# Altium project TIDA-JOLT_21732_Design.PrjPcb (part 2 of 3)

## Sheet JOLT_21732_OI_AIN_PWM_check.SchDoc
size 431 x 279 mm; Date: Not shown in title block; ApprovedBy: Not shown in title block; CheckedBy: Not shown in title block; Author: Not shown in title block; CompanyName: Not shown in title block; DrawnBy: X.Gong; Engineer: Not shown in title block; Organization: Not shown in title block; Address1: Not shown in title block; Address2: Not shown in title block; Address3: Not shown in title block; Address4: Not shown in title block; DocumentNumber: 2; Revision: Use project parameter SCH_Rev; SheetNumber: 2; SheetTotal: 5; PageSetup: Record=PageOptions¦CenterHorizontal=True¦CenterVertical=True¦PrintScale=1.00¦XCorrection=1.00¦YCorrection=1.00¦PrintKind=0¦BorderSize=5000000¦LeftOffset=0¦BottomOffset=0¦Orientation=2¦PaperLength=1000¦PaperWidth=1000¦Scale=100¦PaperSource=15¦PrintQuality=600¦MediaType=1¦DitherType=10¦PaperKind=Letter¦PrintScaleMode=1
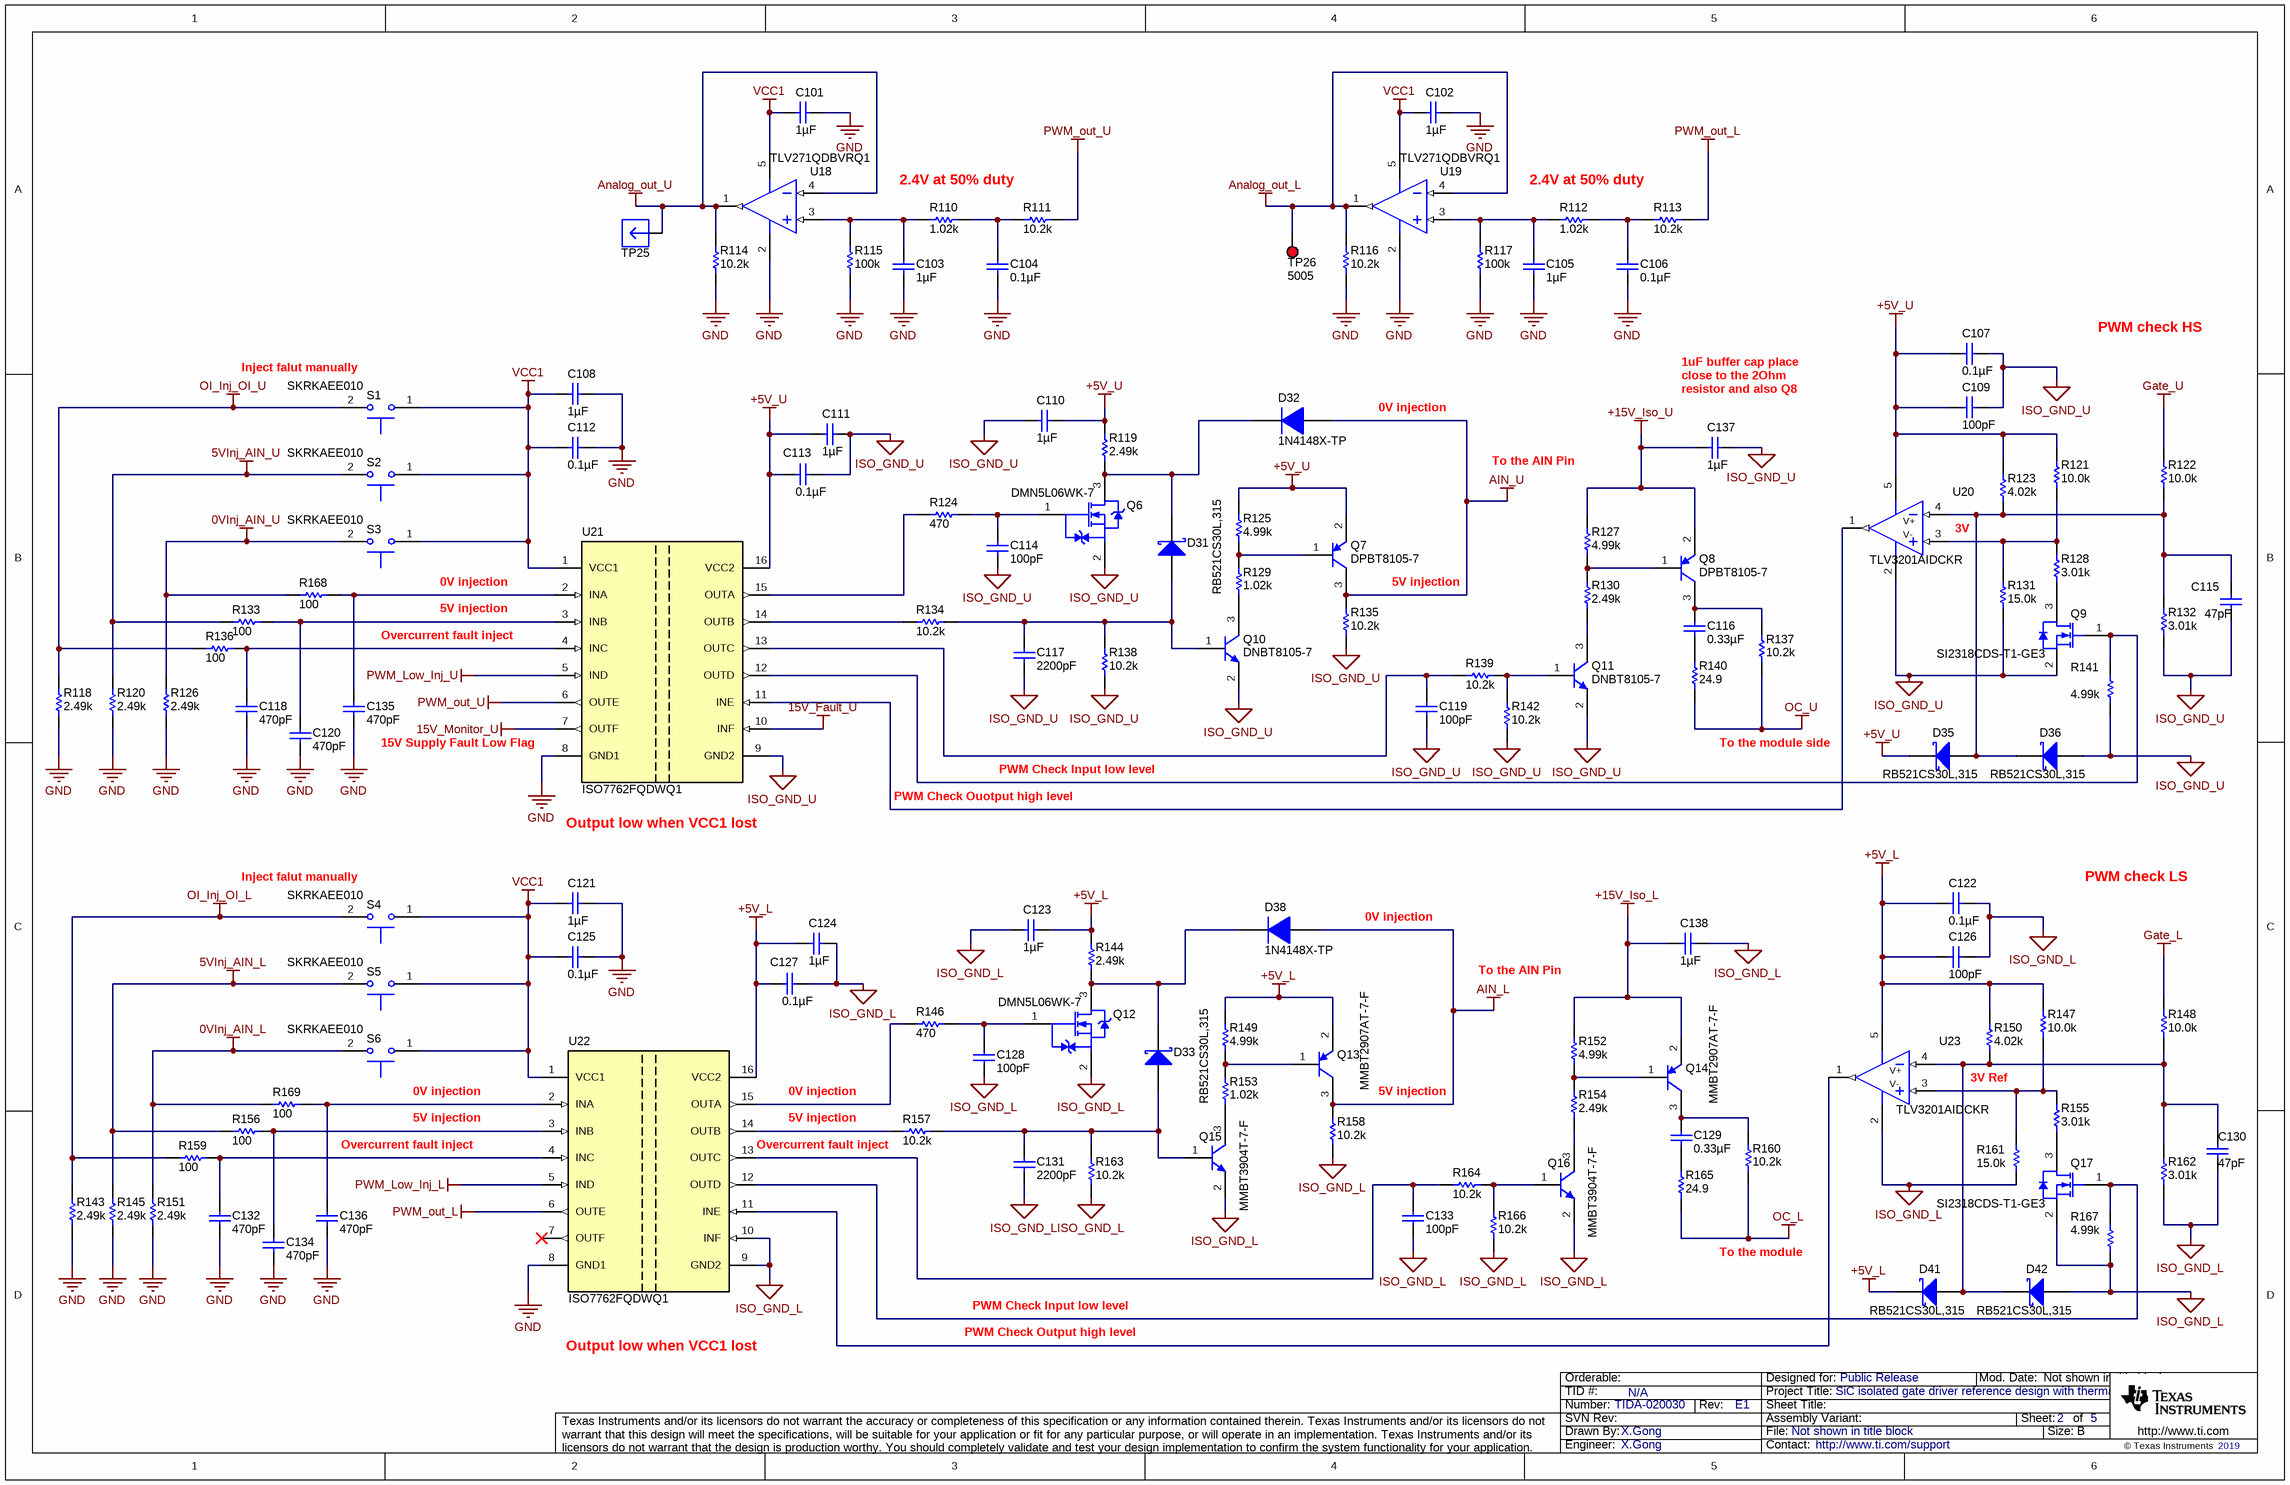
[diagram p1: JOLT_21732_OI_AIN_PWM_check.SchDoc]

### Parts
C101  ValueDisplayed: 1µF  [0603]  (hidden comment: GRM188R71E105KA12D)
C102  ValueDisplayed: 1µF  [0603]  (hidden comment: GRM188R71E105KA12D)
C103  ValueDisplayed: 1µF  [0603]  (hidden comment: GRM188R71E105KA12D)
C104  ValueDisplayed: 0.1µF  [0603]  (hidden comment: GRM188R71H104KA93D)
C105  ValueDisplayed: 1µF  [0603]  (hidden comment: GRM188R71E105KA12D)
C106  ValueDisplayed: 0.1µF  [0603]  (hidden comment: GRM188R71H104KA93D)
C107  ValueDisplayed: 0.1µF  [0603]  (hidden comment: GRM188R71H104KA93D)
C108  ValueDisplayed: 1µF  [0603]  (hidden comment: GRM188R71E105KA12D)
C109  ValueDisplayed: 100pF  [0603]  (hidden comment: GRM1885C1H101JA01D)
C110  ValueDisplayed: 1µF  [0603]  (hidden comment: GRM188R71E105KA12D)
C111  ValueDisplayed: 1µF  [0603]  (hidden comment: GRM188R71E105KA12D)
C112  ValueDisplayed: 0.1µF  [0603]  (hidden comment: GRM188R71H104KA93D)
C113  ValueDisplayed: 0.1µF  [0603]  (hidden comment: GRM188R71H104KA93D)
C114  ValueDisplayed: 100pF  [0603]  (hidden comment: GRM1885C1H101JA01D)
C115  ValueDisplayed: 47pF  [0603]  (hidden comment: GRM1885C1H470JA01D)
C116  ValueDisplayed: 0.33µF  [0805_HV]  (hidden comment: GRM219R71H334KA88D)
C117  ValueDisplayed: 2200pF  [0603]  (hidden comment: GRM188R71E222KA01D)
C118  ValueDisplayed: 470pF  [0603]  (hidden comment: GRM1885C1H471JA01D)
C119  ValueDisplayed: 100pF  [0603]  (hidden comment: GRM1885C1H101JA01D)
C120  ValueDisplayed: 470pF  [0603]  (hidden comment: GRM1885C1H471JA01D)
C121  ValueDisplayed: 1µF  [0603]  (hidden comment: GRM188R71E105KA12D)
C122  ValueDisplayed: 0.1µF  [0603]  (hidden comment: GRM188R71H104KA93D)
C123  ValueDisplayed: 1µF  [0603]  (hidden comment: GRM188R71E105KA12D)
C124  ValueDisplayed: 1µF  [0603]  (hidden comment: GRM188R71E105KA12D)
C125  ValueDisplayed: 0.1µF  [0603]  (hidden comment: GRM188R71H104KA93D)
C126  ValueDisplayed: 100pF  [0603]  (hidden comment: GRM1885C1H101JA01D)
C127  ValueDisplayed: 0.1µF  [0603]  (hidden comment: GRM188R71H104KA93D)
C128  ValueDisplayed: 100pF  [0603]  (hidden comment: GRM1885C1H101JA01D)
C129  ValueDisplayed: 0.33µF  [0805_HV]  (hidden comment: GRM219R71H334KA88D)
C130  ValueDisplayed: 47pF  [0603]  (hidden comment: GRM1885C1H470JA01D)
C131  ValueDisplayed: 2200pF  [0603]  (hidden comment: GRM188R71E222KA01D)
C132  ValueDisplayed: 470pF  [0603]  (hidden comment: GRM1885C1H471JA01D)
C133  ValueDisplayed: 100pF  [0603]  (hidden comment: GRM1885C1H101JA01D)
C134  ValueDisplayed: 470pF  [0603]  (hidden comment: GRM1885C1H471JA01D)
C135  ValueDisplayed: 470pF  [0603]  (hidden comment: GRM1885C1H471JA01D)
C136  ValueDisplayed: 470pF  [0603]  (hidden comment: GRM1885C1H471JA01D)
C137  ValueDisplayed: 1µF  [0603]  (hidden comment: GRM188R71E105KA12D)
C138  ValueDisplayed: 1µF  [0603]  (hidden comment: GRM188R71E105KA12D)
D31  RB521CS30L,315  [SOD882]
D32  1N4148X-TP  [SOD-523]
D33  RB521CS30L,315  [SOD882]
D35  RB521CS30L,315  [SOD882]
D36  RB521CS30L,315  [SOD882]
D38  1N4148X-TP  [SOD-523]
D41  RB521CS30L,315  [SOD882]
D42  RB521CS30L,315  [SOD882]
Q6  DMN5L06WK-7  [SOT-323]
Q7  DPBT8105-7  [SOT-23]
Q8  DPBT8105-7  [SOT-23]
Q9  SI2318CDS-T1-GE3  [SOT-23]
Q10  DNBT8105-7  [SOT-23]
Q11  DNBT8105-7  [SOT-23]
Q12  DMN5L06WK-7  [SOT-323]
Q13  MMBT2907AT-7-F  [SOT-523]
Q14  MMBT2907AT-7-F  [SOT-523]
Q15  MMBT3904T-7-F  [SOT-523]
Q16  MMBT3904T-7-F  [SOT-523]
Q17  SI2318CDS-T1-GE3  [SOT-23]
R110  ValueDisplayed: 1.02k  [0603]  (hidden comment: CRCW06031K02FKEA)
R111  ValueDisplayed: 10.2k  [0603]  (hidden comment: CRCW060310K2FKEA)
R112  ValueDisplayed: 1.02k  [0603]  (hidden comment: CRCW06031K02FKEA)
R113  ValueDisplayed: 10.2k  [0603]  (hidden comment: CRCW060310K2FKEA)
R114  ValueDisplayed: 10.2k  [0603]  (hidden comment: CRCW060310K2FKEA)
R115  ValueDisplayed: 100k  [0603]  (hidden comment: CRCW0603100KFKEA)
R116  ValueDisplayed: 10.2k  [0603]  (hidden comment: CRCW060310K2FKEA)
R117  ValueDisplayed: 100k  [0603]  (hidden comment: CRCW0603100KFKEA)
R118  ValueDisplayed: 2.49k  [0805_HV]  (hidden comment: CRCW08052K49FKEA)
R119  ValueDisplayed: 2.49k  [0805_HV]  (hidden comment: CRCW08052K49FKEA)
R120  ValueDisplayed: 2.49k  [0805_HV]  (hidden comment: CRCW08052K49FKEA)
R121  ValueDisplayed: 10.0k  [0603]  (hidden comment: CRCW060310K0FKEA)
R122  ValueDisplayed: 10.0k  [0805_HV]  (hidden comment: CRCW080510K0FKEA)
R123  ValueDisplayed: 4.02k  [0805_HV]  (hidden comment: CRCW08054K02FKEA)
R124  ValueDisplayed: 470  [0603]  (hidden comment: CRCW0603470RJNEA)
R125  ValueDisplayed: 4.99k  [0603]  (hidden comment: CRCW06034K99FKEA)
R126  ValueDisplayed: 2.49k  [0805_HV]  (hidden comment: CRCW08052K49FKEA)
R127  ValueDisplayed: 4.99k  [0603]  (hidden comment: CRCW06034K99FKEA)
R128  ValueDisplayed: 3.01k  [0805_HV]  (hidden comment: CRCW08053K01FKEA)
R129  ValueDisplayed: 1.02k  [0603]  (hidden comment: CRCW06031K02FKEA)
R130  ValueDisplayed: 2.49k  [0603]  (hidden comment: CRCW06032K49FKEA)
R131  ValueDisplayed: 15.0k  [0603]  (hidden comment: CRCW060315K0FKEA)
R132  ValueDisplayed: 3.01k  [0805_HV]  (hidden comment: CRCW08053K01FKEA)
R133  ValueDisplayed: 100  [0603]  (hidden comment: CRCW0603100RFKEA)
R134  ValueDisplayed: 10.2k  [0603]  (hidden comment: CRCW060310K2FKEA)
R135  ValueDisplayed: 10.2k  [0603]  (hidden comment: CRCW060310K2FKEA)
R136  ValueDisplayed: 100  [0603]  (hidden comment: CRCW0603100RFKEA)
R137  ValueDisplayed: 10.2k  [0603]  (hidden comment: CRCW060310K2FKEA)
R138  ValueDisplayed: 10.2k  [0603]  (hidden comment: CRCW060310K2FKEA)
R139  ValueDisplayed: 10.2k  [0603]  (hidden comment: CRCW060310K2FKEA)
R140  ValueDisplayed: 24.9  [0805_HV]  (hidden comment: CRCW080524R9FKEA)
R141  ValueDisplayed: 4.99k  [0603]  (hidden comment: CRCW06034K99FKEA)
R142  ValueDisplayed: 10.2k  [0603]  (hidden comment: CRCW060310K2FKEA)
R143  ValueDisplayed: 2.49k  [0805_HV]  (hidden comment: CRCW08052K49FKEA)
R144  ValueDisplayed: 2.49k  [0805_HV]  (hidden comment: CRCW08052K49FKEA)
R145  ValueDisplayed: 2.49k  [0805_HV]  (hidden comment: CRCW08052K49FKEA)
R146  ValueDisplayed: 470  [0603]  (hidden comment: CRCW0603470RJNEA)
R147  ValueDisplayed: 10.0k  [0603]  (hidden comment: CRCW060310K0FKEA)
R148  ValueDisplayed: 10.0k  [0805_HV]  (hidden comment: CRCW080510K0FKEA)
R149  ValueDisplayed: 4.99k  [0603]  (hidden comment: CRCW06034K99FKEA)
R150  ValueDisplayed: 4.02k  [0805_HV]  (hidden comment: CRCW08054K02FKEA)
R151  ValueDisplayed: 2.49k  [0805_HV]  (hidden comment: CRCW08052K49FKEA)
R152  ValueDisplayed: 4.99k  [0603]  (hidden comment: CRCW06034K99FKEA)
R153  ValueDisplayed: 1.02k  [0603]  (hidden comment: CRCW06031K02FKEA)
R154  ValueDisplayed: 2.49k  [0603]  (hidden comment: CRCW06032K49FKEA)
R155  ValueDisplayed: 3.01k  [0805_HV]  (hidden comment: CRCW08053K01FKEA)
R156  ValueDisplayed: 100  [0603]  (hidden comment: CRCW0603100RFKEA)
R157  ValueDisplayed: 10.2k  [0603]  (hidden comment: CRCW060310K2FKEA)
R158  ValueDisplayed: 10.2k  [0603]  (hidden comment: CRCW060310K2FKEA)
R159  ValueDisplayed: 100  [0603]  (hidden comment: CRCW0603100RFKEA)
R160  ValueDisplayed: 10.2k  [0603]  (hidden comment: CRCW060310K2FKEA)
R161  ValueDisplayed: 15.0k  [0603]  (hidden comment: CRCW060315K0FKEA)
R162  ValueDisplayed: 3.01k  [0805_HV]  (hidden comment: CRCW08053K01FKEA)
R163  ValueDisplayed: 10.2k  [0603]  (hidden comment: CRCW060310K2FKEA)
R164  ValueDisplayed: 10.2k  [0603]  (hidden comment: CRCW060310K2FKEA)
R165  ValueDisplayed: 24.9  [0805_HV]  (hidden comment: CRCW080524R9FKEA)
R166  ValueDisplayed: 10.2k  [0603]  (hidden comment: CRCW060310K2FKEA)
R167  ValueDisplayed: 4.99k  [0603]  (hidden comment: CRCW06034K99FKEA)
R168  ValueDisplayed: 100  [0603]  (hidden comment: CRCW0603100RFKEA)
R169  ValueDisplayed: 100  [0603]  (hidden comment: CRCW0603100RFKEA)
S1  SKRKAEE010  [SW_SKRKAEE010]
S2  SKRKAEE010  [SW_SKRKAEE010]
S3  SKRKAEE010  [SW_SKRKAEE010]
S4  SKRKAEE010  [SW_SKRKAEE010]
S5  SKRKAEE010  [SW_SKRKAEE010]
S6  SKRKAEE010  [SW_SKRKAEE010]
TP25  0508-0-00-15-00-00-03-0  [Mill-Max_0508-0-00-15-00-00-03-0]  (value not drawn)
TP26  5005  [Keystone5005]
U18  TLV271QDBVRQ1  [DBV0005A_N]
U19  TLV271QDBVRQ1  [DBV0005A_N]
U20  TLV3201AIDCKR  [DCK0005A_N]
U21  ISO7762FQDWQ1  [DW0016B_HV]
U22  ISO7762FQDWQ1  [DW0016B_HV]
U23  TLV3201AIDCKR  [DCK0005A_N]

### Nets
0VInj_AIN_L: R151.1 R169.1 S6.2
0VInj_AIN_U: R126.1 R168.1 S3.2
5VInj_AIN_L: R145.1 R156.1 S5.2
5VInj_AIN_U: R120.1 R133.1 S2.2
15V_Fault_U: U21.10(INF)
15V_Monitor_U: U21.7(OUTF)
+5V_L: C122.2 C123.1 C124.2 C126.1 C127.2 D41.1(K) Q13.2(E) R144.2 R147.2 R149.2 R150.2 U22.16(VCC2) U23.5(V+)
+5V_U: C107.2 C109.1 C110.1 C111.2 C113.2 D35.1(K) Q7.2(E) R119.2 R121.2 R123.2 R125.2 U20.5(V+) U21.16(VCC2)
+15V_Iso_L: C138.1 Q14.2(E) R152.2
+15V_Iso_U: C137.1 Q8.2(E) R127.2
AIN_L: D38.2(A) Q13.3(C) R158.2
AIN_U: D32.2(A) Q7.3(C) R135.2
Analog_out_L: R116.2 TP26.1 U19.1(OUT) U19.4(IN-)
Analog_out_U: R114.2 TP25.1 U18.1(OUT) U18.4(IN-)
Gate_L: R148.2
Gate_U: R122.2
GND: C101.1 C102.1 C103.2 C104.1 C105.2 C106.1 C108.1 C112.2 C118.1 C120.1 C121.1 C125.2 C132.1 C134.1 C135.1 C136.1 R114.1 R115.1 R116.1 R117.1 R118.2 R120.2 R126.2 R143.2 R145.2 R151.2 U18.2(GND) U19.2(GND) U21.8(GND1) U22.8(GND1)
ISO_GND_L: C122.1 C123.2 C124.1 C126.2 C127.1 C128.2 C130.2 C131.2 C133.2 C138.2 D42.2(A) Q12.2(S) Q15.2(E) Q16.2(E) Q17.2(S) R158.1 R161.1 R162.1 R163.1 R166.1 R167.1 U22.9(GND2) U22.10(INF) U23.2(V-)
ISO_GND_U: C107.1 C109.2 C110.2 C111.1 C113.1 C114.2 C115.2 C117.2 C119.2 C137.2 D36.2(A) Q6.2(S) Q9.2(S) Q10.2(E) Q11.2(E) R131.1 R132.1 R135.1 R138.1 R141.1 R142.1 U20.2(V-) U21.9(GND2)
OC_L: R160.1 R165.1
OC_U: R137.1 R140.1
OI_Inj_OI_L: R143.1 R159.1 S4.2
OI_Inj_OI_U: R118.1 R136.1 S1.2
PWM_Low_Inj_L: U22.5(IND)
PWM_Low_Inj_U: U21.5(IND)
PWM_out_L: R113.2 U22.6(OUTE)
PWM_out_U: R111.2 U21.6(OUTE)
VCC1: C101.2 C102.2 C108.2 C112.1 C121.2 C125.1 S1.1 S2.1 S3.1 S4.1 S5.1 S6.1 U18.5(VDD) U19.5(VDD) U21.1(VCC1) U22.1(VCC1)
NetC103_1: C103.1 R110.1 R115.2 U18.3(IN+)
NetC104_2: C104.2 R110.2 R111.1
NetC105_1: C105.1 R112.1 R117.2 U19.3(IN+)
NetC106_2: C106.2 R112.2 R113.1
NetC114_1: C114.1 Q6.1(G) R124.2
NetC115_1: C115.1 D35.2(A) D36.1(K) R122.1 R123.1 R132.2 U20.4(IN-)
NetC116_1: C116.1 Q8.3(C) R137.2
NetC116_2: C116.2 R140.2
NetC117_1: C117.1 D31.2(A) Q10.1(B) R134.2 R138.2
NetC118_2: C118.2 R136.2 U21.4(INC)
NetC119_1: C119.1 R139.1 U21.13(OUTC)
NetC120_2: C120.2 R133.2 U21.3(INB)
NetC128_1: C128.1 Q12.1(G) R146.2
NetC129_1: C129.1 Q14.3(C) R160.2
NetC129_2: C129.2 R165.2
NetC130_1: C130.1 D41.2(A) D42.1(K) R148.1 R150.1 R162.2 U23.4(IN-)
NetC131_1: C131.1 D33.2(A) Q15.1(B) R157.2 R163.2
NetC132_2: C132.2 R159.2 U22.4(INC)
NetC133_1: C133.1 R164.1 U22.13(OUTC)
NetC134_2: C134.2 R156.2 U22.3(INB)
NetC135_2: C135.2 R168.2 U21.2(INA)
NetC136_2: C136.2 R169.2 U22.2(INA)
NetD31_1: D31.1(K) D32.1(K) Q6.3(D) R119.1
NetD33_1: D33.1(K) D38.1(K) Q12.3(D) R144.1
NetQ7_1: Q7.1(B) R125.1 R129.2
NetQ8_1: Q8.1(B) R127.1 R130.2
NetQ9_1: Q9.1(G) R141.2 U21.12(OUTD)
NetQ9_3: Q9.3(D) R128.1
NetQ10_3: Q10.3(C) R129.1
NetQ11_1: Q11.1(B) R139.2 R142.2
NetQ11_3: Q11.3(C) R130.1
NetQ13_1: Q13.1(B) R149.1 R153.2
NetQ14_1: Q14.1(B) R152.1 R154.2
NetQ15_3: Q15.3(C) R153.1
NetQ16_1: Q16.1(B) R164.2 R166.2
NetQ16_3: Q16.3(C) R154.1
NetQ17_1: Q17.1(G) R167.2 U22.12(OUTD)
NetQ17_3: Q17.3(D) R155.1
NetR121_1: R121.1 R128.2 R131.2 U20.3(IN+)
NetR124_1: R124.1 U21.15(OUTA)
NetR134_1: R134.1 U21.14(OUTB)
NetR146_1: R146.1 U22.15(OUTA)
NetR147_1: R147.1 R155.2 R161.2 U23.3(IN+)
NetR157_1: R157.1 U22.14(OUTB)
NetU20_1: U20.1(OUT) U21.11(INE)
NetU22_11: U22.11(INE) U23.1(OUT)

Not connected (* = marked no-connect by the designer): U22 7(OUTF)*

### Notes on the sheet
- 2.4V at 50% duty
- (near S1) Inject falut manually
- PWM check HS
- 0V injection
- (near C137) 1uF buffer cap place close to the 2Ohm resistor and also Q8
- To the AIN Pin
- 3V
- Overcurrent fault inject
- 5V injection
- 15V Supply Fault Low Flag
- PWM Check Input low level
- To the module side
- Output low when VCC1 lost
- PWM Check Ouotput high level
- (near S4) Inject falut manually
- PWM check LS
- (near S6) 0V injection
- (near R150) 3V Ref
- (near R157) Overcurrent fault inject
- To the module
- PWM Check Output high level

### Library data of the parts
C101-C103 C105 C108 C110 C111 C121 C123 C124 C137 C138 = GRM188R71E105KA12D: CAP, CERM, 1 µF, 25 V,+/- 10%, X7R, 0603; Manufacturer: MuRata; Polarized: N; CompType: Capacitor; Value: 1uF; U/M: EA; Cap_F: 0.000001; Tolerance_%: 10; VDC_V: 25; Value2: 25V; TaMin_C: -55; TaMax_C: 125; SizeArea_mm2: 1.28; SizeAreaWB_mm2: 4.68; SizeX_mm: 1.6; SizeY_mm: 0.8; SizeZ_mm: 1; AEC Category: Q200; Green_Lifecycle: Active; Green_REACh: Passed
C104 C106 C107 C112 C113 C122 C125 C127 = GRM188R71H104KA93D: CAP, CERM, 0.1 µF, 50 V,+/- 10%, X7R, 0603; Manufacturer: MuRata; Polarized: N; CompType: Capacitor; Value: 0.1uF; U/M: EA; Cap_F: 0.0000001; Tolerance_%: 10; VDC_V: 50; Value2: 50V; TaMin_C: -55; TaMax_C: 125; SizeArea_mm2: 1.28; SizeAreaWB_mm2: 4.68; SizeX_mm: 1.6; SizeY_mm: 0.8; SizeZ_mm: 1; AEC Category: Q200; Green_Lifecycle: Active; Green_REACh: Passed
C109 C114 C119 C126 C128 C133 = GRM1885C1H101JA01D: CAP, CERM, 100 pF, 50 V,+/- 5%, C0G/NP0, 0603; Manufacturer: MuRata; Polarized: N; CompType: Capacitor; Value: 100pF; U/M: EA; Cap_F: 0.0000000001; Tolerance_%: 5; VDC_V: 50; Value2: 50V; TaMin_C: -55; TaMax_C: 125; SizeArea_mm2: 1.28; SizeAreaWB_mm2: 4.68; SizeX_mm: 1.6; SizeY_mm: 0.8; SizeZ_mm: 1; AEC Category: Q200; Green_Lifecycle: Active; Green_REACh: Passed
C115 C130 = GRM1885C1H470JA01D: CAP, CERM, 47 pF, 50 V,+/- 5%, C0G/NP0, 0603; Manufacturer: MuRata; Polarized: N; CompType: Capacitor; Value: 47pF; U/M: EA; Cap_F: 0.000000000047; Tolerance_%: 5; VDC_V: 50; Value2: 50V; TaMin_C: -55; TaMax_C: 125; SizeArea_mm2: 1.28; SizeAreaWB_mm2: 4.68; SizeX_mm: 1.6; SizeY_mm: 0.8; SizeZ_mm: 1; AEC Category: Q200; Green_Lifecycle: Active; Green_REACh: Passed
C116 C129 = GRM219R71H334KA88D: CAP, CERM, 0.33 µF, 50 V,+/- 10%, X7R, 0805; Manufacturer: MuRata; Polarized: N; CompType: Capacitor; Value: 0.33uF; U/M: EA; Cap_F: 0.00000033; Tolerance_%: 10; VDC_V: 50; Value2: 50V; TaMin_C: -55; TaMax_C: 125; Cap_Case: 0805; SizeArea_mm2: 2.5; SizeAreaWB_mm2: 6.75; SizeX_mm: 2; SizeY_mm: 1.25; SizeZ_mm: 1.45; AEC Category: Q200; Green_Lifecycle: Active; Green_REACh: Passed
C117 C131 = GRM188R71E222KA01D: CAP, CERM, 2200 pF, 25 V,+/- 10%, X7R, 0603; Manufacturer: MuRata; Polarized: N; CompType: Capacitor; Value: 2200pF; U/M: EA; Cap_F: 0.0000000022; Tolerance_%: 10; VDC_V: 25; Value2: 25V; TaMin_C: -55; TaMax_C: 125; SizeArea_mm2: 1.28; SizeAreaWB_mm2: 4.68; SizeX_mm: 1.6; SizeY_mm: 0.8; SizeZ_mm: 1; AEC Category: Q200; Green_Lifecycle: Active; Green_REACh: Passed
C118 C120 C132 C134-C136 = GRM1885C1H471JA01D: CAP, CERM, 470 pF, 50 V,+/- 5%, C0G/NP0, 0603; Manufacturer: MuRata; Polarized: N; CompType: Capacitor; Value: 470pF; U/M: EA; Cap_F: 0.00000000047; Tolerance_%: 5; VDC_V: 50; Value2: 50V; TaMin_C: -55; TaMax_C: 125; SizeArea_mm2: 1.28; SizeAreaWB_mm2: 4.68; SizeX_mm: 1.6; SizeY_mm: 0.8; SizeZ_mm: 1; AEC Category: Q200; Green_Lifecycle: Active; Green_REACh: Passed
D31 D33 D35 D36 D41 D42 = CMP-0028877-2: Diode, Schottky, 30 V, 0.1 A, AEC-Q101, SOD882; Manufacturer: Nexperia; Green_Lifecycle: Not Set; Value2: 0.35V; Vf_V: 3.5dV; Vr_V: 30V; Green_REACh: Incomplete; AEC Category: Q101; Io_A: 1dA; SizeX_mm: 0.985; SizeY_mm: 0.585; SizeArea_mm2: 0.576225; SizeAreaWB_mm2: 3.146225; SizeZ_mm: 0.5; Value: 30V; TJmax_C: 150°C; AEC Qualified: Y; Value1: 0.1A
D32 D38 = CMP-0076957-3: Diode, Switching, 75 V, 0.3 A, SOD-523; Manufacturer: Micro Commercial Components; SizeY_mm: 0.9; Value2: 1.25V; Vr_V: 75V; Value1: 0.3A; Value: 75V; Green_Lifecycle: Not Set; SizeAreaWB_mm2: 5.13; SizeArea_mm2: 1.53; SizeZ_mm: 0.65; Io_A: 3dA; TJmax_C: 150°C; SizeX_mm: 1.7; Green_REACh: Incomplete; AEC Category: Q101
Q6 Q12 = CMP-0000759-1: MOSFET, N-CH, 50 V, 0.3 A, SOT-323; Alternate Manufacturer: None; Manufacturer: Diodes Inc.; SizeZ_mm: 1.1; ChType: N; VdsMax_V: 50V; SizeX_mm: 2.2; Vgs_V: 20V; Value: 50V; SizeArea_mm2: 4.84; AEC Category: Q101; IdsMax_A: 3dA; SizeAreaWB_mm2: 10.24; U/M: EA
Q7 Q8 = CMP-0064870-1: Transistor, PNP, 60 V, 1 A, AEC-Q101, SOT-23; Manufacturer: Diodes Inc.; TaMin_C: -55°C; HfeMax: 300; SizeAreaWB_mm2: 14; Value1: 1 A; Vceo_V: 60V; U/M: EA; Value: 60 V; TaMax_C: 150°C; IcRated_A: 1A; SizeZ_mm: 1.1; SizeX_mm: 2.5; SizeY_mm: 3; SizeArea_mm2: 7.5; CompType: BJT; PNP: 1; AEC Qualified: Y; NPN: 0; Vcesat1_V: 3dV; AEC Category: Q101
Q9 Q17 = CMP-0000739-1: MOSFET, N-CH, 40 V, 5.6 A, SOT-23; Alternate Manufacturer: None; Manufacturer: Vishay-Siliconix; SizeZ_mm: 1.1; ChType: N; Value2: 5.8 nC; Value1: 0.05; VdsMax_V: 40V; SizeX_mm: 2.5; SizeY_mm: 3; Vgs_V: 20V; Value: 40V; Rdson45_ohm: 0.051; SizeArea_mm2: 7.5; AEC Category: Q101; IdsMax_A: 5.6A; SizeAreaWB_mm2: 14; U/M: EA; QgTyp_nC: 5.8
Q10 Q11 = CMP-0064871-1: Transistor, NPN, 60 V, 1 A, AEC-Q101, SOT-23; Manufacturer: Diodes Inc.; TaMin_C: -55°C; HfeMax: 300; Green_Lifecycle: Not Set; SizeAreaWB_mm2: 14; Green_REACh: Incomplete; Value1: 1 A; Vceo_V: 60V; U/M: EA; Value: 60 V; TaMax_C: 150°C; IcRated_A: 1A; SizeZ_mm: 1.1; SizeX_mm: 2.5; SizeY_mm: 3; SizeArea_mm2: 7.5; CompType: BJT; PNP: 0; AEC Qualified: Y; NPN: 1; Vcesat1_V: 2.5dV; AEC Category: Q101
Q13 Q14 = CMP-0000362-2: Transistor, PNP, 60 V, 0.6 A, AEC-Q101, SOT-523; Manufacturer: Diodes Inc.; TaMax_C: 150°C; Value2: 300; Value1: 0.6 A; Vcesat1_V: 4dV; SizeX_mm: 1.6; TaMin_C: -55°C; IcRated_A: 6dA; CompType: BJT; SizeZ_mm: 0.8; AEC Qualified: Y; Value: 60 V; SizeArea_mm2: 2.56; NPN: 0; Vceo_V: 60V; PNP: 1; AEC Category: Q101; SizeAreaWB_mm2: 6.76; U/M: EA
Q15 Q16 = CMP-0000405-2: Transistor, NPN, 40 V, 0.2 A, SOT-523; Manufacturer: Diodes Inc.; TaMax_C: 150°C; Value2: 300; Value1: 0.2 A; Vcesat1_V: 2dV; SizeX_mm: 1.6; TaMin_C: -55°C; IcRated_A: 2dA; CompType: BJT; SizeZ_mm: 0.8; Value: 40 V; SizeArea_mm2: 2.56; NPN: 1; Vceo_V: 40V; PNP: 0; AEC Category: Q101; SizeAreaWB_mm2: 6.76; U/M: EA
R110 R112 R129 R153 = CRCW06031K02FKEA: RES, 1.02 k, 1%, 0.1 W, 0603; Manufacturer: Vishay-Dale; CompType: Resistor; Value: 1.02k; Res_ohm: 1020; Value_Code: 1k02; Tolerance_%: 1; Power_W: 0.1; Value2: 0.1W; VDC_V: 75; TempCo: 100 ppm/C; SizeArea_mm2: 1.28; SizeX_mm: 1.6; SizeY_mm: 0.8; EIA_Code: E96; U/M: EA; AEC Category: Q200; Green_Lifecycle: Active; Green_REACh: Passed
R111 R113 R114 R116 R134 R135 R137-R139 R142 R157 R158 R160 R163 R164 R166 = CRCW060310K2FKEA: RES, 10.2 k, 1%, 0.1 W, 0603; Manufacturer: Vishay-Dale; CompType: Resistor; Value: 10.2k; Res_ohm: 10200; Value_Code: 10k2; Tolerance_%: 1; Power_W: 0.1; Value2: 0.1W; VDC_V: 75; TempCo: 100 ppm/C; SizeArea_mm2: 1.28; SizeX_mm: 1.6; SizeY_mm: 0.8; EIA_Code: E96; U/M: EA; AEC Category: Q200; Green_Lifecycle: Active; Green_REACh: Passed
R115 R117 = CRCW0603100KFKEA: RES, 100 k, 1%, 0.1 W, 0603; Manufacturer: Vishay-Dale; CompType: Resistor; Value: 100k; Res_ohm: 100000; Tolerance_%: 1; Power_W: 0.1; Value2: 0.1W; VDC_V: 75; TempCo: 100 ppm/C; SizeArea_mm2: 1.28; SizeX_mm: 1.6; SizeY_mm: 0.8; EIA_Code: E96; U/M: EA; AEC Category: Q200; Green_Lifecycle: Active; Green_REACh: Passed
R118-R120 R126 R143-R145 R151 = CRCW08052K49FKEA: RES, 2.49 k, 1%, 0.125 W, 0805; Manufacturer: Vishay-Dale; CompType: Resistor; Value: 2.49k; Res_ohm: 2490; Value_Code: 2k49; Tolerance_%: 1; Power_W: 0.125; Value2: 0.125W; VDC_V: 150; TempCo: 100 ppm/C; SizeArea_mm2: 2.5; SizeX_mm: 2; SizeY_mm: 1.25; SizeZ_mm: 1.45; EIA_Code: E96; U/M: EA; AEC Category: Q200; Green_Lifecycle: Active; Green_REACh: Passed
R121 R147 = CRCW060310K0FKEA: RES, 10.0 k, 1%, 0.1 W, 0603; Manufacturer: Vishay-Dale; CompType: Resistor; Value: 10.0k; Res_ohm: 10000; Value_Code: 10k0; Tolerance_%: 1; Power_W: 0.1; Value2: 0.1W; VDC_V: 75; TempCo: 100 ppm/C; SizeArea_mm2: 1.28; SizeX_mm: 1.6; SizeY_mm: 0.8; EIA_Code: E96; U/M: EA; AEC Category: Q200; Green_Lifecycle: Active; Green_REACh: Passed
R122 R148 = CRCW080510K0FKEA: RES, 10.0 k, 1%, 0.125 W, 0805; Manufacturer: Vishay-Dale; CompType: Resistor; Value: 10.0k; Res_ohm: 10000; Value_Code: 10k0; Tolerance_%: 1; Power_W: 0.125; Value2: 0.125W; VDC_V: 150; TempCo: 100 ppm/C; SizeArea_mm2: 2.5; SizeX_mm: 2; SizeY_mm: 1.25; SizeZ_mm: 1.45; EIA_Code: E96; U/M: EA; AEC Category: Q200; Green_Lifecycle: Active; Green_REACh: Passed
R123 R150 = CRCW08054K02FKEA: RES, 4.02 k, 1%, 0.125 W, 0805; Manufacturer: Vishay-Dale; CompType: Resistor; Value: 4.02k; Res_ohm: 4020; Value_Code: 4k02; Tolerance_%: 1; Power_W: 0.125; Value2: 0.125W; VDC_V: 150; TempCo: 100 ppm/C; SizeArea_mm2: 2.5; SizeX_mm: 2; SizeY_mm: 1.25; SizeZ_mm: 1.45; EIA_Code: E96; U/M: EA; AEC Category: Q200; Green_Lifecycle: Active; Green_REACh: Passed
R124 R146 = CRCW0603470RJNEA: RES, 470, 5%, 0.1 W, 0603; Manufacturer: Vishay-Dale; CompType: Resistor; Value: 470; Value_Code: 470R; Tolerance_%: 5; Power_W: 0.1; Value2: 0.1W; VDC_V: 75; TempCo: 200 ppm/C; SizeArea_mm2: 1.28; SizeX_mm: 1.6; SizeY_mm: 0.8; SizeZ_mm: 1; EIA_Code: E24; U/M: EA; AEC Category: Q200; Green_Lifecycle: Active; Green_REACh: Passed
R125 R127 R141 R149 R152 R167 = CRCW06034K99FKEA: RES, 4.99 k, 1%, 0.1 W, 0603; Manufacturer: Vishay-Dale; CompType: Resistor; Value: 4.99k; Res_ohm: 4990; Value_Code: 4k99; Tolerance_%: 1; Power_W: 0.1; Value2: 0.1W; VDC_V: 75; TempCo: 100 ppm/C; SizeArea_mm2: 1.28; SizeX_mm: 1.6; SizeY_mm: 0.8; EIA_Code: E96; U/M: EA; AEC Category: Q200; Green_Lifecycle: Active; Green_REACh: Passed
R128 R132 R155 R162 = CRCW08053K01FKEA: RES, 3.01 k, 1%, 0.125 W, 0805; Manufacturer: Vishay-Dale; CompType: Resistor; Value: 3.01k; Res_ohm: 3010; Value_Code: 3k01; Tolerance_%: 1; Power_W: 0.125; Value2: 0.125W; VDC_V: 150; TempCo: 100 ppm/C; SizeArea_mm2: 2.5; SizeX_mm: 2; SizeY_mm: 1.25; SizeZ_mm: 1.45; EIA_Code: E96; U/M: EA; AEC Category: Q200; Green_Lifecycle: Active; Green_REACh: Passed
R130 R154 = CRCW06032K49FKEA: RES, 2.49 k, 1%, 0.1 W, 0603; Manufacturer: Vishay-Dale; CompType: Resistor; Value: 2.49k; Res_ohm: 2490; Value_Code: 2k49; Tolerance_%: 1; Power_W: 0.1; Value2: 0.1W; VDC_V: 75; TempCo: 100 ppm/C; SizeArea_mm2: 1.28; SizeX_mm: 1.6; SizeY_mm: 0.8; EIA_Code: E96; U/M: EA; AEC Category: Q200; Green_Lifecycle: Active; Green_REACh: Passed
R131 R161 = CRCW060315K0FKEA: RES, 15.0 k, 1%, 0.1 W, 0603; Manufacturer: Vishay-Dale; CompType: Resistor; Value: 15.0k; Res_ohm: 15000; Value_Code: 15k0; Tolerance_%: 1; Power_W: 0.1; Value2: 0.1W; VDC_V: 75; TempCo: 100 ppm/C; SizeArea_mm2: 1.28; SizeX_mm: 1.6; SizeY_mm: 0.8; EIA_Code: E96; U/M: EA; AEC Category: Q200; Green_Lifecycle: Active; Green_REACh: Passed
R133 R136 R156 R159 R168 R169 = CRCW0603100RFKEA: RES, 100, 1%, 0.1 W, 0603; Manufacturer: Vishay-Dale; CompType: Resistor; Value: 100; Value_Code: 100R; Tolerance_%: 1; Power_W: 0.1; Value2: 0.1W; VDC_V: 75; TempCo: 100 ppm/C; SizeArea_mm2: 1.28; SizeX_mm: 1.6; SizeY_mm: 0.8; EIA_Code: E96; U/M: EA; AEC Category: Q200; Green_Lifecycle: Active; Green_REACh: Passed
R140 R165 = CRCW080524R9FKEA: RES, 24.9, 1%, 0.125 W, 0805; Manufacturer: Vishay-Dale; CompType: Resistor; Value: 24.9; Value_Code: 24R9; Tolerance_%: 1; Power_W: 0.125; Value2: 0.125W; VDC_V: 150; TempCo: 100 ppm/C; SizeArea_mm2: 2.5; SizeX_mm: 2; SizeY_mm: 1.25; SizeZ_mm: 1.45; EIA_Code: E96; U/M: EA; AEC Category: Q200; Green_Lifecycle: Active; Green_REACh: Passed
S1-S6 = CMP-0002113-2: Switch, Push Button, SMD; Manufacturer: Alps; CurrentRating_mA: 50A; SwitchFunction: Off-Mom; Circuit: SPST-NO; VDC_V: 12V; PositionCount: 1
TP25 = CMP-0055027-1: PCB Pin, 20mil Dia, Gold, TH; Manufacturer: Mill-Max; CNHeader: FALSE; Gender: Male; CompType: PCB Pin
TP26 = CMP-0055142-1: Test Point, Compact, Red, TH; Manufacturer: Keystone; CNHeader: FALSE; Green_Lifecycle: Active; Green_REACh: Passed; ContactFinish: Silver; CT: TRUE
U18 U19 = CMP-0042686-1: Automotive Catalog 550 uA/Ch, 3 MHz, Rail-to-Rail Output Operational Amplifier, 2.7 to 16 V, -40 to 125 degC, 5-pin SOT23 (DBV5), Green (RoHS & no Sb/Br); Manufacturer: Texas Instruments; Vio (25C)(Max)(mV): 5; CMRR(Min)(dB): 58; Total Supply Voltage(Min)(+5V is 5, +/-5V is 10): 2.7; Packing: LARGE T&R; Iq per channel(Max)(mA): 0.66; Total Supply Voltage(Max)(+5V is 5, +/-5V is 10): 16; Sub Family: Low Supply Voltage Amplifier (<=2.7V), Precision Amplifier; Slew Rate(Typ)(V/us): 2.4; Offset Drift(Typ)(uV/C): 2; GBW(Typ)(MHz): 3; Number of Channels: 1; IIB(Max)(pA): 60
U20 U23 = CMP-0073518-3: 40ns, micro-Power, Rail-to-Rail Input, Single-Channel Comparator with Push-Pull Outputs, DCK0005A (SOT-SC70-5); Alternate PartNumber: TLV3201AIDCKT; Alternate Manufacturer: Texas Instruments; SizeAreaWB_mm2: 9.3; SizeZ_mm: 1.1; SizeX_mm: 2.1; SizeY_mm: 2.0; SizeArea_mm2: 4.2; CompType: IC; AEC Category: Q200; AEC Qualified: N
U21 U22 = CMP-0860136-1: Automotive, High Speed, Robust EMC Six-Channel Digital Isolators, DW0016B (SOIC-16); Alternate Manufacturer: Texas Instruments; Alternate PartNumber: ISO7762FQDWRQ1; SizeAreaWB_mm2: 152.52; SizeY_mm: 10.3; CompType: IC; AEC Qualified: Y; SizeArea_mm2: 107.12; SizeZ_mm: 2.65; AEC Category: Q200; SizeX_mm: 10.4

## Sheet JOLT_21732_DCbus_Thermal_LS.SchDoc
size 431 x 279 mm; Date: Not shown in title block; ApprovedBy: Not shown in title block; CheckedBy: Not shown in title block; Author: Not shown in title block; CompanyName: Not shown in title block; DrawnBy: X.Gong; Engineer: Not shown in title block; Organization: Not shown in title block; Address1: Not shown in title block; Address2: Not shown in title block; Address3: Not shown in title block; Address4: Not shown in title block; DocumentNumber: 3; Revision: Use project parameter SCH_Rev; SheetNumber: 3; SheetTotal: 5; PageSetup: Record=PageOptions¦CenterHorizontal=True¦CenterVertical=True¦PrintScale=1.00¦XCorrection=1.00¦YCorrection=1.00¦PrintKind=0¦BorderSize=5000000¦LeftOffset=0¦BottomOffset=0¦Orientation=2¦PaperLength=1000¦PaperWidth=1000¦Scale=100¦PaperSource=15¦PrintQuality=600¦MediaType=1¦DitherType=10¦PaperKind=Letter¦PrintScaleMode=1
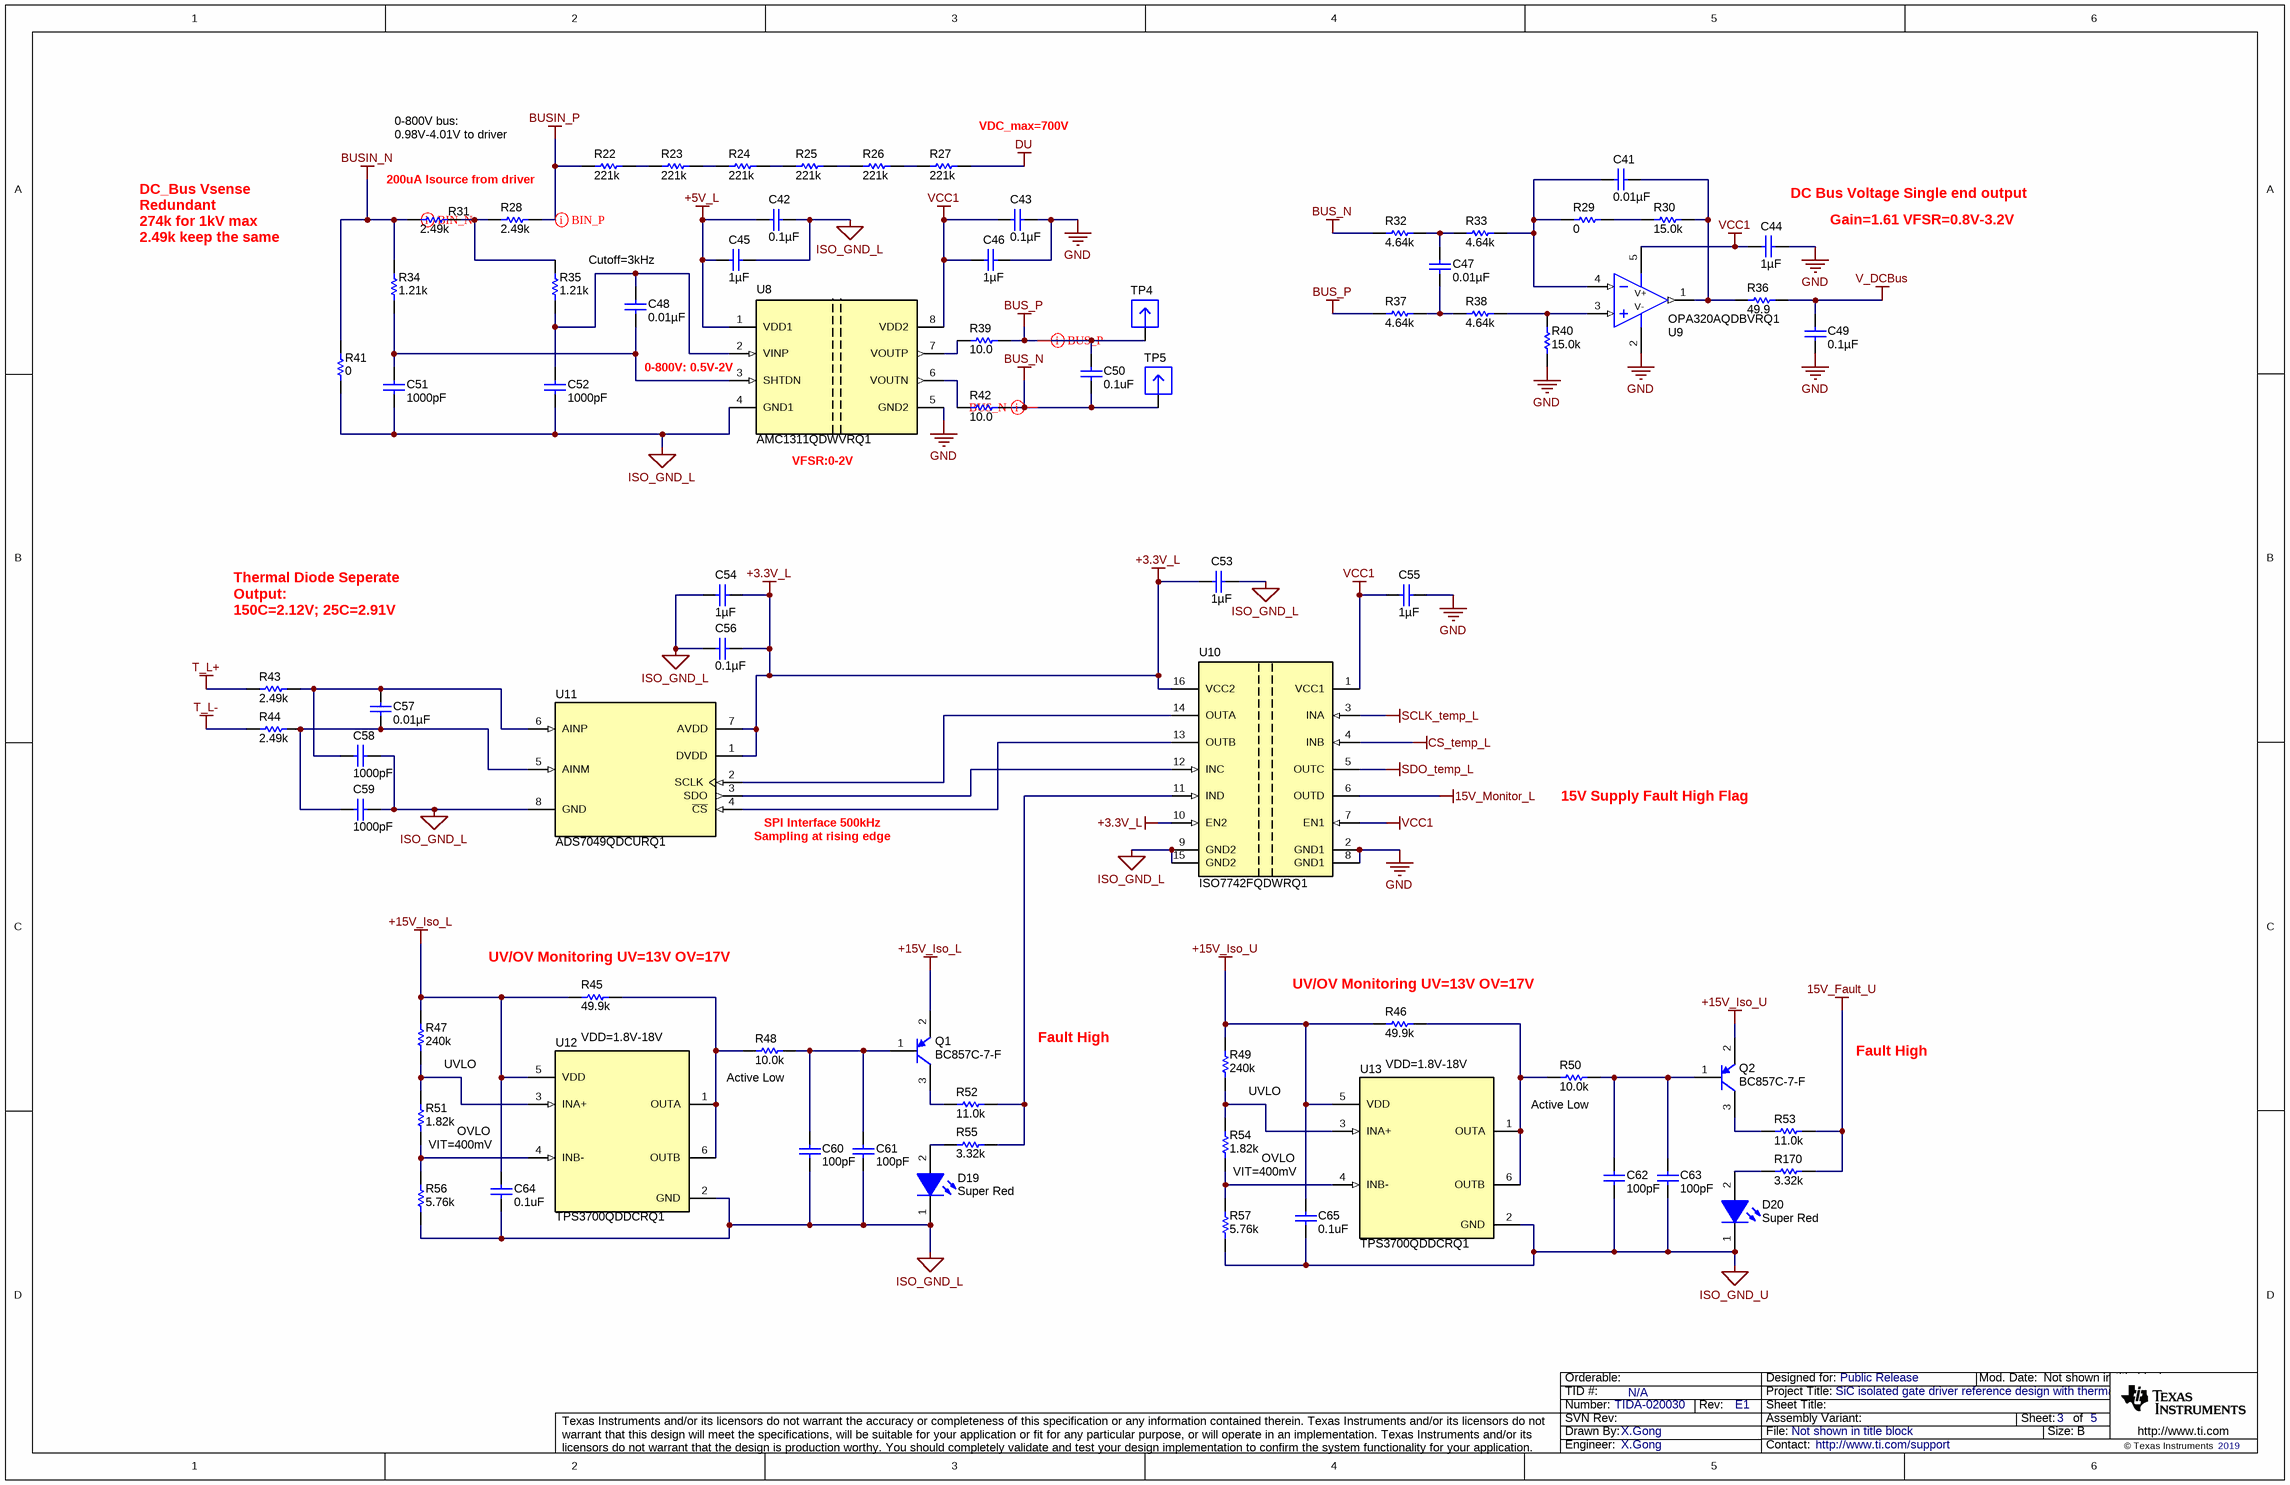
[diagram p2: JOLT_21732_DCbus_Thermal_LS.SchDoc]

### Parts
C41  ValueDisplayed: 0.01µF  [0603]  (hidden comment: GRM188R71H103KA01D)
C42  ValueDisplayed: 0.1µF  [0603]  (hidden comment: GRM188R71H104KA93D)
C43  ValueDisplayed: 0.1µF  [0603]  (hidden comment: GRM188R71H104KA93D)
C44  ValueDisplayed: 1µF  [0603]  (hidden comment: GRM188R71E105KA12D)
C45  ValueDisplayed: 1µF  [0603]  (hidden comment: GRM188R71E105KA12D)
C46  ValueDisplayed: 1µF  [0603]  (hidden comment: GRM188R71E105KA12D)
C47  ValueDisplayed: 0.01µF  [0603]  (hidden comment: GRM188R71H103KA01D)
C48  ValueDisplayed: 0.01µF  [0603]  (hidden comment: GRM188R71H103KA01D)
C49  ValueDisplayed: 0.1µF  [0603]  (hidden comment: GRM188R71H104KA93D)
C50  ValueDisplayed: 0.1uF  [0402]  (hidden comment: Capacitor)
C51  ValueDisplayed: 1000pF  [0603]  (hidden comment: GRM188R71H102KA01D)
C52  ValueDisplayed: 1000pF  [0603]  (hidden comment: GRM188R71H102KA01D)
C53  ValueDisplayed: 1µF  [0603]  (hidden comment: GRM188R71E105KA12D)
C54  ValueDisplayed: 1µF  [0603]  (hidden comment: GRM188R71E105KA12D)
C55  ValueDisplayed: 1µF  [0603]  (hidden comment: GRM188R71E105KA12D)
C56  ValueDisplayed: 0.1µF  [0603]  (hidden comment: GRM188R71H104KA93D)
C57  ValueDisplayed: 0.01µF  [0603]  (hidden comment: GRM188R71H103KA01D)
C58  ValueDisplayed: 1000pF  [0603]  (hidden comment: GRM188R71H102KA01D)
C59  ValueDisplayed: 1000pF  [0603]  (hidden comment: GRM188R71H102KA01D)
C60  ValueDisplayed: 100pF  [0603]  (hidden comment: GRM1885C2A101JA01D)
C61  ValueDisplayed: 100pF  [0603]  (hidden comment: GRM1885C2A101JA01D)
C62  ValueDisplayed: 100pF  [0603]  (hidden comment: GRM1885C2A101JA01D)
C63  ValueDisplayed: 100pF  [0603]  (hidden comment: GRM1885C2A101JA01D)
C64  ValueDisplayed: 0.1uF  [0402]  (hidden comment: Capacitor)
C65  ValueDisplayed: 0.1uF  [0402]  (hidden comment: Capacitor)
D19  value Super Red  [WL-SMCW_RED]  (hidden comment: 150060SS75000)
D20  value Super Red  [WL-SMCW_RED]  (hidden comment: 150060SS75000)
Q1  BC857C-7-F  [SOT-23]
Q2  BC857C-7-F  [SOT-23]
R22  ValueDisplayed: 221k  [1206]  (hidden comment: CRCW1206221KFKEA)
R23  ValueDisplayed: 221k  [1206]  (hidden comment: CRCW1206221KFKEA)
R24  ValueDisplayed: 221k  [1206]  (hidden comment: CRCW1206221KFKEA)
R25  ValueDisplayed: 221k  [1206]  (hidden comment: CRCW1206221KFKEA)
R26  ValueDisplayed: 221k  [1206]  (hidden comment: CRCW1206221KFKEA)
R27  ValueDisplayed: 221k  [1206]  (hidden comment: CRCW1206221KFKEA)
R28  ValueDisplayed: 2.49k  [0805_HV]  (hidden comment: CRCW08052K49FKEA)
R29  ValueDisplayed: 0  [0603]  (hidden comment: CRCW06030000Z0EA)
R30  ValueDisplayed: 15.0k  [0603]  (hidden comment: CRCW060315K0FKEA)
R31  ValueDisplayed: 2.49k  [0805_HV]  (hidden comment: CRCW08052K49FKEA)
R32  ValueDisplayed: 4.64k  [0603]  (hidden comment: CRCW06034K64FKEA)
R33  ValueDisplayed: 4.64k  [0603]  (hidden comment: CRCW06034K64FKEA)
R34  ValueDisplayed: 1.21k  [0603]  (hidden comment: CRCW06031K21FKEA)
R35  ValueDisplayed: 1.21k  [0603]  (hidden comment: CRCW06031K21FKEA)
R36  ValueDisplayed: 49.9  [0603]  (hidden comment: CRCW060349R9FKEA)
R37  ValueDisplayed: 4.64k  [0603]  (hidden comment: CRCW06034K64FKEA)
R38  ValueDisplayed: 4.64k  [0603]  (hidden comment: CRCW06034K64FKEA)
R39  ValueDisplayed: 10.0  [0402]  (hidden comment: CRCW040210R0FKED)
R40  ValueDisplayed: 15.0k  [0603]  (hidden comment: CRCW060315K0FKEA)
R41  ValueDisplayed: 0  [0402]  (hidden comment: CRCW04020000Z0ED)
R42  ValueDisplayed: 10.0  [0402]  (hidden comment: CRCW040210R0FKED)
R43  ValueDisplayed: 2.49k  [0603]  (hidden comment: CRCW06032K49FKEA)
R44  ValueDisplayed: 2.49k  [0603]  (hidden comment: CRCW06032K49FKEA)
R45  ValueDisplayed: 49.9k  [0402]  (hidden comment: CRCW040249K9FKED)
R46  ValueDisplayed: 49.9k  [0402]  (hidden comment: CRCW040249K9FKED)
R47  ValueDisplayed: 240k  [0402]  (hidden comment: CRCW0402240KFKED)
R48  ValueDisplayed: 10.0k  [0402]  (hidden comment: CRCW040210K0FKED)
R49  ValueDisplayed: 240k  [0402]  (hidden comment: CRCW0402240KFKED)
R50  ValueDisplayed: 10.0k  [0402]  (hidden comment: CRCW040210K0FKED)
R51  ValueDisplayed: 1.82k  [0402]  (hidden comment: CRCW04021K82FKED)
R52  ValueDisplayed: 11.0k  [0603]  (hidden comment: CRCW060311K0FKEA)
R53  ValueDisplayed: 11.0k  [0603]  (hidden comment: CRCW060311K0FKEA)
R54  ValueDisplayed: 1.82k  [0402]  (hidden comment: CRCW04021K82FKED)
R55  ValueDisplayed: 3.32k  [0603]  (hidden comment: CRCW06033K32FKEA)
R56  ValueDisplayed: 5.76k  [0402]  (hidden comment: CRCW04025K76FKED)
R57  ValueDisplayed: 5.76k  [0402]  (hidden comment: CRCW04025K76FKED)
R170  ValueDisplayed: 3.32k  [0603]  (hidden comment: CRCW06033K32FKEA)
TP4  0508-0-00-15-00-00-03-0  [Mill-Max_0508-0-00-15-00-00-03-0]  (value not drawn)
TP5  0508-0-00-15-00-00-03-0  [Mill-Max_0508-0-00-15-00-00-03-0]  (value not drawn)
U8  PartNumber: AMC1311QDWVRQ1  [DWV0008A]  (hidden comment: AMC1311DWVR)
U9  OPA320AQDBVRQ1  [DBV0005A_N]
U10  ISO7742FQDWRQ1  [DW0016B_HV]
U11  ADS7049QDCURQ1  [DCU0008A_N]
U12  TPS3700QDDCRQ1  [DDC0006A_N]
U13  TPS3700QDDCRQ1  [DDC0006A_N]

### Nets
15V_Fault_U: R53.2 R170.2
15V_Monitor_L: U10.6(OUTD)
+3.3V_L: C53.2 C54.1 C56.2 U10.10(EN2) U10.16(VCC2) U11.1(DVDD) U11.7(AVDD)
+5V_L: C42.1 C45.2 U8.1(VDD1)
+15V_Iso_L: C64.1 Q1.2(E) R45.1 R47.2 U12.5(VDD)
+15V_Iso_U: C65.1 Q2.2(E) R46.1 R49.2 U13.5(VDD)
BUS_N: C50.2 R32.1 R42.1 TP5.1
BUS_P: C50.1 R37.1 R39.1 TP4.1
BUSIN_N: R31.1 R34.2 R41.2
BUSIN_P: R22.1 R28.2
CS_temp_L: U10.4(INB)
DU: R27.2
GND: C43.2 C44.1 C46.1 C49.2 C55.1 R40.1 U8.5(GND2) U9.2(V-) U10.2(GND1) U10.8(GND1)
ISO_GND_L: C42.2 C45.1 C51.2 C52.2 C53.1 C54.2 C56.1 C58.1 C59.1 C60.2 C61.2 C64.2 D19.1(K) R41.1 R56.1 U8.4(GND1) U10.9(GND2) U10.15(GND2) U11.8(GND) U12.2(GND)
ISO_GND_U: C62.2 C63.2 C65.2 D20.1(K) R57.1 U13.2(GND)
SCLK_temp_L: U10.3(INA)
SDO_temp_L: U10.5(OUTC)
T_L+: R43.1
T_L-: R44.1
V_DCBus: C49.1 R36.1
VCC1: C43.1 C44.2 C46.2 C55.2 U8.8(VDD2) U9.5(V+) U10.1(VCC1) U10.7(EN1)
NetC41_1: C41.1 R29.1 R33.2 U9.4(IN-)
NetC41_2: C41.2 R30.2 R36.2 U9.1(OUT)
NetC47_1: C47.1 R32.2 R33.1
NetC47_2: C47.2 R37.2 R38.1
NetC48_1: C48.1 C51.1 R34.1 U8.3(SHTDN)
NetC48_2: C48.2 C52.1 R35.1 U8.2(VINP)
NetC57_1: C57.1 C59.2 R44.2 U11.5(AINM)
NetC57_2: C57.2 C58.2 R43.2 U11.6(AINP)
NetC60_1: C60.1 C61.1 Q1.1(B) R48.2
NetC62_1: C62.1 C63.1 Q2.1(B) R50.2
NetD19_2: D19.2(A) R55.1
NetD20_2: D20.2(A) R170.1
NetQ1_3: Q1.3(C) R52.1
NetQ2_3: Q2.3(C) R53.1
NetR22_2: R22.2 R23.1
NetR23_2: R23.2 R24.1
NetR24_2: R24.2 R25.1
NetR25_2: R25.2 R26.1
NetR26_2: R26.2 R27.1
NetR28_1: R28.1 R31.2 R35.2
NetR29_2: R29.2 R30.1
NetR38_2: R38.2 R40.2 U9.3(IN+)
NetR39_2: R39.2 U8.7(VOUTP)
NetR42_2: R42.2 U8.6(VOUTN)
NetR45_2: R45.2 R48.1 U12.1(OUTA) U12.6(OUTB)
NetR46_2: R46.2 R50.1 U13.1(OUTA) U13.6(OUTB)
NetR47_1: R47.1 R51.2 U12.3(INA+)
NetR49_1: R49.1 R54.2 U13.3(INA+)
NetR51_1: R51.1 R56.2 U12.4(INB-)
NetR52_2: R52.2 R55.2 U10.11(IND)
NetR54_1: R54.1 R57.2 U13.4(INB-)
NetU10_12: U10.12(INC) U11.3(SDO)
NetU10_13: U10.13(OUTB) U11.4(~{CS})
NetU10_14: U10.14(OUTA) U11.2(SCLK)

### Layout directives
differential pair: BUS_N, BUS_P, BUSIN_N, BUSIN_P

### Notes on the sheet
- 0-800V bus:
  0.98V-4.01V to driver
- (near R27) VDC_max=700V
- 200uA Isource from driver
- (near C44) DC Bus Voltage Single end output
- Gain=1.61 VFSR=0.8V-3.2V
- DC_Bus Vsense Redundant
  274k for 1kV max
  2.49k keep the same
- Cutoff=3kHz
- (near U8) 0-800V: 0.5V-2V
- (near U8) VFSR:0-2V
- Thermal Diode Seperate
  Output:
  150C=2.12V; 25C=2.91V
- (near U11) SPI Interface 500kHz
- (near U11) Sampling at rising edge
- 15V Supply Fault High Flag
- (near R45) UV/OV Monitoring UV=13V OV=17V
- VDD=1.8V-18V
- Fault High
- (near R46) UV/OV Monitoring UV=13V OV=17V
- UVLO
- (near R48) Active Low
- (near R50) Active Low
- (near R51) VIT=400mV
- OVLO
- (near R54) VIT=400mV

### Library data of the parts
C41 C47 C48 C57 = GRM188R71H103KA01D: CAP, CERM, 0.01 µF, 50 V,+/- 10%, X7R, 0603; Manufacturer: MuRata; Polarized: N; CompType: Capacitor; Value: 0.01uF; U/M: EA; Cap_F: 0.00000001; Tolerance_%: 10; VDC_V: 50; Value2: 50V; TaMin_C: -55; TaMax_C: 125; SizeArea_mm2: 1.28; SizeAreaWB_mm2: 4.68; SizeX_mm: 1.6; SizeY_mm: 0.8; SizeZ_mm: 1; AEC Category: Q200; Green_Lifecycle: Active; Green_REACh: Passed
C42 C43 C49 C56 = GRM188R71H104KA93D: as C104 on sheet JOLT_21732_OI_AIN_PWM_check
C44-C46 C53-C55 = GRM188R71E105KA12D: as C101-C103 on sheet JOLT_21732_OI_AIN_PWM_check
C50 = CMP-0006297-2: CAP, CERM, 0.1 uF, 50 V, +/- 10%, X7R, 0402; PartNumber: C1005X7R1H104K050BB; Manufacturer: TDK; Polarized: N; Value: 0.1uF; U/M: EA; Cap_F: 100nF; ESR_ohm: 0.039064; Value1: 0.039064 ohm; VDC_V: 50V; IRMS_A: 8.14669dA; TaMin_C: -55°C; TaMax_C: 125°C; SizeArea_mm2: 0.5; SizeAreaWB_mm2: 3; SizeX_mm: 1; SizeZ_mm: 0.6; AEC Category: Q200
C51 C52 C58 C59 = GRM188R71H102KA01D: CAP, CERM, 1000 pF, 50 V,+/- 10%, X7R, 0603; Manufacturer: MuRata; Polarized: N; CompType: Capacitor; Value: 1000pF; U/M: EA; Cap_F: 0.000000001; Tolerance_%: 10; VDC_V: 50; Value2: 50V; TaMin_C: -55; TaMax_C: 125; SizeArea_mm2: 1.28; SizeAreaWB_mm2: 4.68; SizeX_mm: 1.6; SizeY_mm: 0.8; SizeZ_mm: 1; AEC Category: Q200; Green_Lifecycle: Active; Green_REACh: Passed
C60-C63 = GRM1885C2A101JA01D: CAP, CERM, 100 pF, 100 V,+/- 5%, C0G/NP0, 0603; Manufacturer: MuRata; Polarized: N; CompType: Capacitor; Value: 100pF; U/M: EA; Cap_F: 0.0000000001; Tolerance_%: 5; VDC_V: 100; Value2: 100V; TaMin_C: -55; TaMax_C: 125; SizeArea_mm2: 1.28; SizeAreaWB_mm2: 4.68; SizeX_mm: 1.6; SizeY_mm: 0.8; SizeZ_mm: 1; AEC Category: Q200; Green_Lifecycle: Active; Green_REACh: Passed
C64 C65 = CMP-0006562-2: CAP, CERM, 0.1 uF, 10 V, +/- 10%, X5R, 0402; PartNumber: GRM155R61A104KA01D; Manufacturer: MuRata; Polarized: N; Value: 0.1uF; U/M: EA; Cap_F: 100nF; Value1: Unknown; VDC_V: 10V; TaMin_C: -55°C; TaMax_C: 85°C; SizeArea_mm2: 0.5; SizeAreaWB_mm2: 3; SizeX_mm: 1; SizeZ_mm: 0.6; AEC Category: Q200
D19 D20 = 150060SS75000: LED, Super Red, SMD; Manufacturer: Wurth Elektronik; Type: AlInGaP; Vf_V: 1.9; Value2: 1.9V; Io_A: 0.02; Value1: W; U/M: EA; Green_Lifecycle: Active; Green_REACh: Passed
Q1 Q2 = BC857C-7-F, Diodes Inc.: Transistor, PNP, 45 V, 0.1 A, SOT-23; CompType: BJT; PNP: 1; NPN: 0; Vceo_V: 45; Vcesat1_V: 0.075; Value: 45 V; IcRated_A: 0.1; Value1: 0.1 A; HfeMax: 600; TaMin_C: -65; TaMax_C: 150; U/M: EA; AEC Category: Q101
R22-R27 = CRCW1206221KFKEA: RES, 221 k, 1%, 0.25 W, 1206; Manufacturer: Vishay-Dale; CompType: Resistor; Value: 221k; Res_ohm: 221000; Tolerance_%: 1; Power_W: 0.25; Value2: 0.25W; VDC_V: 200; TempCo: 100 ppm/C; SizeArea_mm2: 5.12; SizeX_mm: 3.2; SizeY_mm: 1.6; SizeZ_mm: 1.35; EIA_Code: E96; U/M: EA; AEC Category: Q200
R28 R31 = CRCW08052K49FKEA: as R118 on sheet JOLT_21732_OI_AIN_PWM_check
R29 = CRCW06030000Z0EA: RES, 0, 5%, 0.1 W, 0603; Manufacturer: Vishay-Dale; CompType: Resistor; Value: 0; Value_Code: 0000; Tolerance_%: 5; Power_W: 0.1; Value2: 0.1W; VDC_V: 75; TempCo: 200 ppm/C; SizeArea_mm2: 1.28; SizeX_mm: 1.6; SizeY_mm: 0.8; SizeZ_mm: 1; EIA_Code: E24; U/M: EA; AEC Category: Q200; Green_Lifecycle: Active; Green_REACh: Passed
R30 R40 = CRCW060315K0FKEA: as R131 on sheet JOLT_21732_OI_AIN_PWM_check
R32 R33 R37 R38 = CRCW06034K64FKEA: RES, 4.64 k, 1%, 0.1 W, 0603; Manufacturer: Vishay-Dale; CompType: Resistor; Value: 4.64k; Res_ohm: 4640; Value_Code: 4k64; Tolerance_%: 1; Power_W: 0.1; Value2: 0.1W; VDC_V: 75; TempCo: 100 ppm/C; SizeArea_mm2: 1.28; SizeX_mm: 1.6; SizeY_mm: 0.8; EIA_Code: E96; U/M: EA; AEC Category: Q200; Green_Lifecycle: Active; Green_REACh: Passed
R34 R35 = CRCW06031K21FKEA: RES, 1.21 k, 1%, 0.1 W, 0603; Manufacturer: Vishay-Dale; CompType: Resistor; Value: 1.21k; Res_ohm: 1210; Value_Code: 1k21; Tolerance_%: 1; Power_W: 0.1; Value2: 0.1W; VDC_V: 75; TempCo: 100 ppm/C; SizeArea_mm2: 1.28; SizeX_mm: 1.6; SizeY_mm: 0.8; EIA_Code: E96; U/M: EA; AEC Category: Q200; Green_Lifecycle: Active; Green_REACh: Passed
R36 = CRCW060349R9FKEA: RES, 49.9, 1%, 0.1 W, 0603; Manufacturer: Vishay-Dale; CompType: Resistor; Value: 49.9; Value_Code: 49R9; Tolerance_%: 1; Power_W: 0.1; Value2: 0.1W; VDC_V: 75; TempCo: 100 ppm/C; SizeArea_mm2: 1.28; SizeX_mm: 1.6; SizeY_mm: 0.8; EIA_Code: E96; U/M: EA; AEC Category: Q200; Green_Lifecycle: Active; Green_REACh: Passed
R39 R42 = CMP-0025963-2: RES, 10.0, 1%, 0.063 W, 0402; Manufacturer: Vishay-Dale; Power_W: 63mW; TempCo: 100 ppm/C; Value_Code: 10R0; U/M: EA; Value: 10.0; EIA_Code: E96; Res_ohm: 10; SizeX_mm: 1; SizeY_mm: 0.5; SizeZ_mm: 0.6; Value2: 0.063W; CompType: Resistor; VDC_V: 50V; AEC Category: Q200
R41 = CMP-0026822-3: RES, 0, 5%, 0.063 W, AEC-Q200 Grade 0, 0402; Manufacturer: Vishay-Dale; Power_W: 63mW; TempCo: 200 ppm/C; Value_Code: 0000; Value: 0; EIA_Code: E24; SizeX_mm: 1; SizeY_mm: 0.5; SizeZ_mm: 0.6; Value2: 0.063W; CompType: Resistor; AEC Qualified: Y; VDC_V: 50V; AEC Category: Q200
R43 R44 = CRCW06032K49FKEA: as R130 on sheet JOLT_21732_OI_AIN_PWM_check
R45 R46 = CMP-0026403-1: RES, 49.9 k, 1%, 0.063 W, 0402; Manufacturer: Vishay-Dale; Power_W: 63mW; TempCo: 100 ppm/C; Value_Code: 49k9; U/M: EA; Value: 49.9k; EIA_Code: E96; SizeX_mm: 1; SizeY_mm: 0.5; SizeZ_mm: 0.6; Value2: 0.063W; VDC_V: 50V; AEC Category: Q200
R47 R49 = CRCW0402240KFKED: RES, 240 k, 1%, 0.063 W, 0402; Manufacturer: Vishay-Dale; CompType: Resistor; Value: 240k; Res_ohm: 240000; Tolerance_%: 1; Power_W: 0.063; Value2: 0.063W; VDC_V: 50; TempCo: 100 ppm/C; SizeArea_mm2: 0.5; SizeZ_mm: 0.6; U/M: EA; AEC Category: Q200; Green_Lifecycle: Active; Green_REACh: Passed
R48 R50 = CRCW040210K0FKED: RES, 10.0 k, 1%, 0.063 W, 0402; Manufacturer: Vishay-Dale; CompType: Resistor; Value: 10.0k; Res_ohm: 10000; Value_Code: 10k0; Tolerance_%: 1; Power_W: 0.063; Value2: 0.063W; VDC_V: 50; TempCo: 100 ppm/C; SizeArea_mm2: 0.5; SizeZ_mm: 0.6; EIA_Code: E96; U/M: EA; AEC Category: Q200; Green_Lifecycle: Active; Green_REACh: Passed
R51 R54 = CRCW04021K82FKED: RES, 1.82 k, 1%, 0.063 W, 0402; Manufacturer: Vishay-Dale; CompType: Resistor; Value: 1.82k; Res_ohm: 1820; Value_Code: 1k82; Tolerance_%: 1; Power_W: 0.063; Value2: 0.063W; VDC_V: 50; TempCo: 100 ppm/C; SizeArea_mm2: 0.5; SizeZ_mm: 0.6; EIA_Code: E96; U/M: EA; AEC Category: Q200; Green_Lifecycle: Active; Green_REACh: Passed
R52 R53 = CRCW060311K0FKEA: RES, 11.0 k, 1%, 0.1 W, 0603; Manufacturer: Vishay-Dale; CompType: Resistor; Value: 11.0k; Res_ohm: 11000; Value_Code: 11k0; Tolerance_%: 1; Power_W: 0.1; Value2: 0.1W; VDC_V: 75; TempCo: 100 ppm/C; SizeArea_mm2: 1.28; SizeX_mm: 1.6; SizeY_mm: 0.8; EIA_Code: E96; U/M: EA; AEC Category: Q200; Green_Lifecycle: Not Set; Green_REACh: Incomplete
R55 R170 = CRCW06033K32FKEA: RES, 3.32 k, 1%, 0.1 W, 0603; Manufacturer: Vishay-Dale; CompType: Resistor; Value: 3.32k; Res_ohm: 3320; Value_Code: 3k32; Tolerance_%: 1; Power_W: 0.1; Value2: 0.1W; VDC_V: 75; TempCo: 100 ppm/C; SizeArea_mm2: 1.28; SizeX_mm: 1.6; SizeY_mm: 0.8; EIA_Code: E96; U/M: EA; AEC Category: Q200; Green_Lifecycle: Active; Green_REACh: Passed
R56 R57 = CRCW04025K76FKED: RES, 5.76 k, 1%, 0.063 W, 0402; Manufacturer: Vishay-Dale; CompType: Resistor; Value: 5.76k; Res_ohm: 5760; Value_Code: 5k76; Tolerance_%: 1; Power_W: 0.063; Value2: 0.063W; VDC_V: 50; TempCo: 100 ppm/C; SizeArea_mm2: 0.5; SizeZ_mm: 0.6; EIA_Code: E96; U/M: EA; AEC Category: Q200
TP4 TP5 = CMP-0055027-1: as TP25 on sheet JOLT_21732_OI_AIN_PWM_check
U8 = CMP-0013503-2: Precision, 2-V Input, Reinforced Isolated Amplifier, DWV0008A (SOIC-8); Manufacturer: Texas Instruments; SizeX_mm: 11.5; SizeY_mm: 5.85; CompType: IC; SizeZ_mm: 2.8; SizeArea_mm2: 67.275; SizeAreaWB_mm2: 105.975; U/M: EA
U9 = CMP-0077859-1: Automotive Qualified Precision, Zero-Crossover, 20MHz, 0.9pA Ib, RRIO, CMOS Operational Amplifier, DBV0005A (SOT-23-5); Alternate PartNumber: OPA320AQDBVTQ1; Alternate Manufacturer: Texas Instruments; SizeAreaWB_mm2: 14.82; SizeZ_mm: 1.45; SizeX_mm: 2.8; SizeY_mm: 2.9; SizeArea_mm2: 8.12; CompType: IC; AEC Qualified: Y; AEC Category: Q200
U10 = CMP-0076066-3: Automotive, High Speed, Robust EMC Quad-Channel Digital Isolators, DW0016B (SOIC-16); Alternate Manufacturer: Texas Instruments; Alternate PartNumber: ISO7742FQDWQ1; SizeX_mm: 10.4; SizeArea_mm2: 107.12; SizeZ_mm: 2.65; SizeY_mm: 10.3; AEC Category: Q200; AEC Qualified: Y; CompType: IC; SizeAreaWB_mm2: 152.52
U11 = CMP-0075945-2: Ultra-Low-Power Ultra-Small-Size 12-Bit 2MSPS SAR ADC, DCU0008A (VSSOP-8); Manufacturer: Texas Instruments; SizeAreaWB_mm2: 12.6; SizeArea_mm2: 6.4; SizeZ_mm: 0.9; SizeY_mm: 2.0; CompType: IC; SizeX_mm: 3.2; AEC Category: Q200; AEC Qualified: Y; Rating: Automotive
U12 U13 = CMP-0067337-2: Automotive, High-Voltage (18V) Window Comparator with Over- and Undervoltage Detection, DDC0006A (SOT-23-T-6); Manufacturer: Texas Instruments; SizeZ_mm: 0.87; SizeX_mm: 1.65; SizeY_mm: 2.95; SizeArea_mm2: 4.8675; CompType: IC; U/M: EA; SizeAreaWB_mm2: 10.4675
